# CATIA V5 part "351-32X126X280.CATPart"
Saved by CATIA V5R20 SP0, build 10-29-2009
Part number: 351-32X126X280
Definition: NONE
Nomenclature: 351-32X126X280
Source: Unknown
Description: 351-32X126X280
Bounding box of the stored display mesh (mm): x -7 to 273, y -22.5 to 22.5, z -22.5 to 22.5
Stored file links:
  C:\Users\Utente\Desktop\IO LAVORO\3D X SITO CF\X SITO\PLASTICA\351\351-32X126X280.CATPart
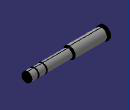
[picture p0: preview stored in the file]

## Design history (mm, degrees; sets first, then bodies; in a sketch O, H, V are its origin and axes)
Body1 "351-32X126X280" (main body)
  Solid1: solid without history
